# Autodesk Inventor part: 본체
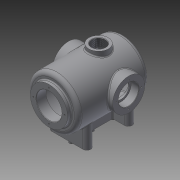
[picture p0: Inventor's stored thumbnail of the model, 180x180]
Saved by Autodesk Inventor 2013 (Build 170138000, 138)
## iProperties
Created: 2016-02
Part Number: 본체
Material: 일반
Document SubType Name: Modeling
Designer: mduedu
Density: 2.71 g/cm^3
Mass: 3248.02 g
Surface Area: 2109.22 cm^2
Volume: 1198.53 cm^3
Author: mduedu
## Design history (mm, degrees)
sketch "스케치2"
  geometry: L1 (0, 100)-(0, -100); L2 (65, -75.993)-(65, 100); L3 (65, 100)-(0, 100); A1 r 100 centre (0, 0) between (0, -100) and (65, -75.993); 2 further points
  constraints: 6 end point, 2 midpoint, 2 point on circle, 1 centre point, 1 coincident, 1 horizontal, 1 parallel, 1 vertical
  dimensions: "d3" = 200 distance of L1.start L1.end; "d5" = 130 diameter of L2 L1; "d6" = 100 radius of A1
revolve "회전1" sketch "스케치2" stored, may be unused: angle "d7" = 90 deg
sketch "스케치3"
  geometry: C1 r 47.5 at (0, 0); 1 further point
  constraints: 1 centre point, 1 coincident
  dimensions: "d8" = 95 diameter of C1
extrude "돌출2" join sketch "스케치3" distance "d10" = 10; taper "d11" = 0 deg
sketch "스케치5"
  geometry: L1 (47.5, 110)-(47.5, 100) reference; L2 (47.5, 100)-(65, 100) reference; L3 (65, 100)-(65, -75.993) reference; L4 (-65, -75.993)-(-65, 100) reference; L5 (-65, 100)-(-47.5, 100) reference; L6 (-47.5, 100)-(-47.5, 110) reference; L7 (-47.5, 110)-(47.5, 110) reference; L8 (55, 85)-(55, -71.239); L9 (0, 85)-(55, 85); L10 (0, 85)-(0, -90); A1 r 100 centre (0, 0) between (0, -100) and (65, -75.993) reference; A2 r 100 centre (0, 0) between (-65, -75.993) and (0, -100) reference; A3 r 90 centre (0, 0) between (0, -90) and (55, -71.239); 1 further point
  constraints: 6 end point, 2 point on circle, 1 centre point, 1 parallel, 1 perpendicular, 1 point on line, 1 vertical
  dimensions: "d13" = 10 distance between parallel lines of L3 L8; "d14" = 10 radial gap between concentric circles of A3 A1; "d15" = 15 distance between parallel lines of L9 L2
revolve "회전2" sketch "스케치5" stored, may be unused: angle "d16" = 90 deg
hole "구멍1" diameter "d19" = 65; stored, may be unused: countersink angle "d23" = 90 deg, drill point angle "d25" = 118 deg; dims "d17" = 10, "d18" = 10, "d20" = 6, "d21" = 4, "d22" = 2, "d24" = 8
node "작업 평면1"
sketch "스케치6"
  geometry: L1 (47.5, 110)-(-47.5, 110) reference; C1 r 41 at (0, -17); 1 further point
  constraints: 1 centre point, 1 vertical alignment
  dimensions: "d27" = 82 diameter of C1; "d29" = 127 distance from line of C1.centre L1
extrude "돌출3" join sketch "스케치6" stored distance "d30" = 10; taper "d31" = 0 deg
hole "구멍2" diameter "d34" = 42; stored, may be unused: countersink angle "d38" = 90 deg, drill point angle "d40" = 118 deg; dims "d35" = 6, "d36" = 52, "d37" = 20, "d39" = 8, "d180" = 10, "d181" = 10
sketch "스케치7" dims "d41" = 65
  geometry: C1 r 41 at (0, 0) reference; 3 further points
  constraints: 2 vertical alignment, 1 coincident, 2 other
hole "구멍3" sketch "스케치7" at (0, 32.5) diameter "d43" = 3.242; stored, may be unused: countersink angle "d47" = 90 deg, drill point angle "d49" = 118 deg; dims "d44" = 11, "d45" = 13, "d46" = 18, "d48" = 13
sketch "스케치8" dims "d53" = 80
  geometry: 3 further points
  constraints: 2 vertical alignment, 1 coincident, 2 other
hole "구멍4" sketch "스케치8" at (0, 40) diameter "d56" = 3.242; stored, may be unused: countersink angle "d60" = 90 deg, drill point angle "d62" = 118 deg; dims "d57" = 11, "d58" = 13, "d59" = 18, "d61" = 13
fillet "모깎기1" dims "d66" = 10
fillet "모깎기2" dims "d67" = 3
fillet "모깎기3" dims "d68" = 0.3
chamfer "모따기1" distance "d69" = 1; stored, may be unused: second distance "d70" = 2, angle "d71" = 45 deg
node "작업 평면5"
sketch "스케치10"
  geometry: L1 (-50, -63)-(50, -63); L2 (50, -63)-(50, -43); L3 (50, -43)-(-50, -43); L4 (-50, -43)-(-50, -63); L5 (-50, 0)-(50, 0); L6 (-50, 63)-(50, 63); L7 (50, 63)-(50, 43); L8 (50, 43)-(-50, 43); L9 (-50, 43)-(-50, 63); 2 further points
  constraints: 18 end point, 4 symmetric about line, 2 parallel, 2 perpendicular, 1 coincident, 1 horizontal, 1 midpoint
  dimensions: "d80" = 20 distance of L3.end L1.start; "d82" = 100 distance of L1.start L1.end; "d130" = 43 vertical distance of L3.end point (0, 0); "d131" = 50 horizontal distance of L3.end point (0, 0); "d132" = 100 distance of L5.start L5.end
extrude "돌출5" join sketch "스케치10" stored distance "d84" = 10; taper "d85" = 0 deg
sketch "스케치11"
  geometry: L1 (-100, -43)-(-100, 43); L2 (-65, 90)-(-65, -71.239) reference; L3 (-100, -43)-(-41.533, -43) reference; L4 (-100, 43)-(-41.533, 43) reference; 1 further point
  constraints: 2 end point, 1 point on line, 1 vertical
feature "리브1" sketch "스케치11" dims "d88" = 1, "d89" = 20, "d90" = 0, "d91" = 0, "d92" = 1, "d93" = 1
fillet "모깎기12"
fillet "모깎기13"
fillet "모깎기14"
fillet "모깎기15"
fillet "모깎기16" dims "d167" = 3
fillet "모깎기17" dims "d168" = 3
node "작업 평면6"
sketch "스케치19"
  geometry: L1 (77, -58)-(77, 24) reference; L2 (-77, -58)-(-77, 24) reference; L3 (77, -17)-(-77, -17); C1 r 25 at (0, -17); 1 further point
  constraints: 3 midpoint, 2 end point, 1 centre point
  dimensions: "d149" = 50 diameter of C1
extrude "돌출11" join sketch "스케치19" stored distance "d150" = 10; taper "d151" = 0 deg
hole "구멍6" diameter "d154" = 35; stored, may be unused: countersink angle "d158" = 90 deg, drill point angle "d160" = 118 deg; dims "d152" = 10, "d153" = 10, "d155" = 6, "d156" = 4, "d157" = 2, "d159" = 8
fillet "모깎기11" dims "d161" = 3
feature "스레드1" dims "d162" = 10, "d163" = 0
chamfer "모따기3" distance "d164" = 1; stored, may be unused: second distance "d165" = 2, angle "d166" = 45 deg
sketch "스케치20"
  geometry: L1 (10, 40)-(10, -40) reference; L2 (13, -43)-(40, -43) reference; L3 (40, -63)-(-40, -63) reference; L4 (-40, -43)-(-13, -43) reference; L5 (-10, -40)-(-10, 40) reference; L6 (-13, 43)-(-40, 43) reference; L7 (-40, 63)-(40, 63) reference; L8 (40, 43)-(13, 43) reference; L9 (-40, 53)-(40, 53); L10 (-40, -53)-(40, -53); L11 (0, 53)-(0, -53); C1 r 5 at (0, 53); C2 r 5 at (0, 0); C3 r 5 at (0, -53); A1 r 3 centre (13, -40) between (10, -40) and (13, -43) reference; A2 r 10 centre (40, -53) between (40, -63) and (40, -43) reference; A3 r 10 centre (-40, -53) between (-40, -43) and (-40, -63) reference; A4 r 3 centre (-13, -40) between (-13, -43) and (-10, -40) reference; A5 r 3 centre (-13, 40) between (-10, 40) and (-13, 43) reference; A6 r 10 centre (-40, 53) between (-40, 63) and (-40, 43) reference; A7 r 10 centre (40, 53) between (40, 43) and (40, 63) reference; A8 r 3 centre (13, 40) between (13, 43) and (10, 40) reference; 1 further point
  constraints: 6 end point, 3 centre point, 3 coincident, 2 midpoint, 2 parallel
  dimensions: "d169" = 10 diameter of C1; "d170" = 10 diameter of C2; "d171" = 10 diameter of C3
extrude "돌출12" join sketch "스케치20" distance "d172" = 10; taper "d173" = 0 deg
chamfer "모따기4" distance "d174" = 1; stored, may be unused: second distance "d175" = 2, angle "d176" = 45 deg
node "솔리드2"
pattern_circular "원형 패턴1" dims angle "d51" = 360 deg
mirror "대칭1"
pattern_circular "원형 패턴2" dims angle "d64" = 360 deg
node "절단 모서리 투영1"
node "절단 모서리 투영4"
other parameters: "d26" = 77, "d136" = 175
